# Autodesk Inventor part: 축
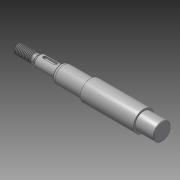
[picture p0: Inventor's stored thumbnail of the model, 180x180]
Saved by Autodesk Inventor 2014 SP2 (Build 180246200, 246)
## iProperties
Created: 2015-11
Part Number: 축
Material: 강철, 연강
Document SubType Name: Modeling
Designer: mduedu
Density: 1 g/cm^3
Appearance: 강철
Author: mduedu
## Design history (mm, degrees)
sketch "스케치1"
  geometry: L1 (-86, 0)-(86, 0); L2 (-86, 0)-(-86, 4); L3 (-86, 4)-(-70.732, 4); L4 (-70.732, 4)-(-69, 3); L5 (-69, 3)-(-67, 3); L6 (-67, 3)-(-67, 5); L7 (-67, 5)-(-49, 5); L8 (-49, 5)-(-49, 6.55); L9 (-47.355, 7.5)-(-23, 7.5); L10 (-23, 7.5)-(-23, 9); L11 (0, 0)-(0, 9); L12 (86, 4)-(70.732, 4); L13 (70.732, 4)-(69, 3); L14 (69, 3)-(67, 3); L15 (67, 3)-(67, 5); L16 (67, 5)-(49, 5); L17 (23, 7.5)-(23, 9); L18 (86, 0)-(86, 4); L19 (-23, 9)-(23, 9); L20 (-49, 6.55)-(-47.355, 7.5); L21 (47.355, 7.5)-(23, 7.5); L22 (49, 6.55)-(47.355, 7.5); L23 (49, 5)-(49, 6.55); 1 further point
  constraints: 46 end point, 10 symmetric about line, 6 perpendicular, 5 parallel, 2 midpoint, 1 coincident, 1 horizontal
  dimensions: "d0" = 172 distance of L1.start L1.end (derived); "d1" = 8 diameter of L3 L1; "d2" = 30 deg angle of L4 L5; "d3" = 6 diameter of L5 L1; "d4" = 10 diameter of L7 L1; "d5" = 15 diameter of L9 L1; "d6" = 18 diameter of L19 L1; "d8" = 18 distance of L6.end L7.end; "d9" = 46 distance of L10.end L17.end; "d10" = 2 distance of L4.end L5.end; "d11" = 17 distance from line of L4.end L2; "d16" = 13.1 diameter of L8.end L1; "d17" = 30 deg angle of L20 L9; "d18" = 26 distance between parallel lines of L10 L8
revolve "회전1" sketch "스케치1" stored, may be unused: angle "d12" = 90 deg
chamfer "모따기1" distance "d13" = 0.5; stored, may be unused: second distance "d14" = 2, angle "d15" = 45 deg
fillet "모깎기1" dims "d19" = 4, "d20" = 0.5
node "작업 평면1"
sketch "스케치2" dims "d23" = 12
  geometry: L1 (-4.5, 1.5)-(4.5, 1.5); L2 (4.5, 1.5)-(4.5, -1.5); L3 (4.5, -1.5)-(-4.5, -1.5); L4 (-4.5, -1.5)-(-4.5, 1.5); L5 (-9, -4.5)-(-9, 4.5) reference; 3 further points
  constraints: 8 end point, 2 midpoint, 2 parallel, 2 vertical alignment, 1 horizontal, 1 perpendicular, 4 other
  dimensions: "d21" = 3 distance between parallel lines of L3 L1; "d24" = 3 dimension on L5
extrude "돌출1" cut sketch "스케치2" distance "d25" = 1.8; taper "d26" = 0 deg
feature "스레드1" dims "d27" = 10, "d28" = 0
feature "스레드2" dims "d29" = 10, "d30" = 0
chamfer "모따기2" distance "d31" = 0.5; stored, may be unused: second distance "d32" = 2, angle "d33" = 45 deg
node "작업 평면2"
sketch "스케치3"
  geometry: C1 r 7.5 at (0, 0) reference; 1 further point
extrude "돌출2" cut sketch "스케치3" stored distance "d36" = 10; taper "d37" = 0 deg
chamfer "모따기3" distance "d38" = 0.5; stored, may be unused: second distance "d39" = 2, angle "d40" = 45 deg
fillet "모깎기3" dims "d41" = 0.6
node "솔리드1"
mirror "대칭1"
node "절단 모서리 투영1"
other parameters: "d35" = 16
